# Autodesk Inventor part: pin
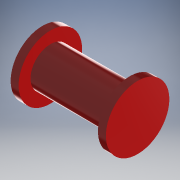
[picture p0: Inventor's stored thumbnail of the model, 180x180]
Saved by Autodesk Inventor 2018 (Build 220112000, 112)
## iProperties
Created: 2023-12
Part Number: pin
Material: Generic
Document SubType Name: Modeling
Designer: DDUGKY
Density: 1 g/cm^3
Appearance: Default
Author: DDUGKY
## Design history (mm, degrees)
sketch "Sketch1"
  geometry: C1 r 10 at (0, 0); 1 further point
  constraints: 1 centre point, 1 coincident
  dimensions: "d0" = 20 diameter of C1
extrude "Extrusion1" new body sketch "Sketch1" stored distance "d1" = 30; taper "d2" = 0 deg
sketch "Sketch3"
  geometry: C1 r 6.25 at (0, 0); C2 r 10 at (0, 0); 1 further point
  constraints: 2 centre point, 2 coincident
  dimensions: "d8" = 12.5 diameter of C1
extrude "Extrusion4" cut sketch "Sketch3" stored distance "d9" = 25; taper "d10" = 0 deg
body "Solid1"
